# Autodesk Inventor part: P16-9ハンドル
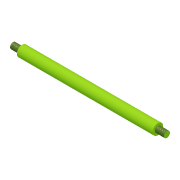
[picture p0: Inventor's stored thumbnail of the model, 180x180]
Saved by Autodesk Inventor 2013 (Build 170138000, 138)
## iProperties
Created: 2008-07
Part Number: P16-9ハンドル
Document SubType Name: Modeling
Designer: y-shimohigashi
Density: 1 g/cm^3
Material: 一般
Author: y-shimohigashi
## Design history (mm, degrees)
sketch "スケッチ1"
  geometry: L1 (-102, 0)-(102, 0); L2 (-102, 0)-(-102, 4); L3 (-102, 4)-(-90, 4); L4 (-90, 4)-(-90, 7); L5 (-90, 7)-(90, 7); L6 (90, 7)-(90, 4); L7 (90, 4)-(102, 4); L8 (102, 4)-(102, 0); 2 further points
  constraints: 16 end point, 4 parallel, 3 collinear, 2 perpendicular, 1 coincident, 1 horizontal, 1 midpoint
  dimensions: "d0" = 7 distance between parallel lines of L1 L5; "d1" = 4 distance of L7.end L1.end; "d2" = 180 distance of L4.end L5.end; "d3" = 12 distance of L6.end L7.end
revolve "回転1" sketch "スケッチ1" stored, may be unused: angle "d4" = 90 deg
feature "ねじ1" dims "d5" = 10, "d6" = 0
feature "ねじ2" dims "d7" = 10, "d8" = 0
node "ソリッド1"
node "ソリッド ボディ"
node "サーフェス ボディ"
